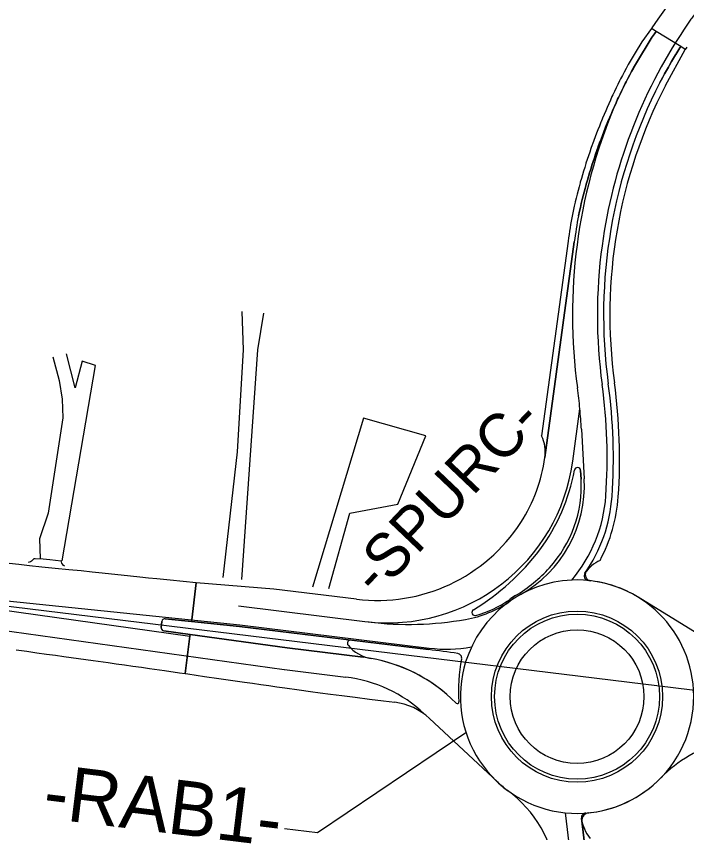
# Model space of a CAD drawing. Extents: x 1756435 to 1766932, y 416863 to 426859.
# Drawn here: x 1761886 to 1762317, y 423810 to 424335 of the extents above; entities that cross this region are included whole.
import ezdxf

# ---------------------------------------------------------------- set-up
doc = ezdxf.new("R2010")
doc.units = 0
for name, color, linetype in [('Exist Roads EOP', 7, 'Continuous'), ('Exist Roads EOP Other', 7, 'Continuous'), ('Exist Roads Soil', 7, 'Continuous'), ('Prop Horizontal Alignment', 7, 'Continuous'), ('Prop Horizontal Alignment Station Label', 7, 'Continuous'), ('Prop Lane Lines', 7, 'Continuous'), ('Prop Shade Light', 7, 'Continuous'), ('Prop Shade Medium', 7, 'Continuous'), ('Sheet Data Field CELL', 7, 'Continuous')]:
    doc.layers.add(name, color=color, linetype=linetype)

msp = doc.modelspace()

# ---------------------------------------------------------------- linework, layer by layer
at = {"layer": 'Exist Roads EOP'}
for points in [[(1762321.6, 424363.48), (1762316.63, 424357.5), (1762311.93, 424351.7), (1762307.26, 424345.52), (1762302.62, 424339), (1762298.3, 424332.9), (1762294.34, 424327.33), (1762294.14, 424327.04)], [(1762316.84, 424314.92), (1762315.88, 424313.48)], [(1762001.76, 423970.65), (1761993.3, 423971.54), (1761985.03, 423972.36), (1761976.32, 423973.22), (1761971.13, 423973.75), (1761965.4, 423974.36), (1761959.38, 423975), (1761953.37, 423975.64), (1761947.35, 423976.28), (1761941.34, 423976.92), (1761934.94, 423977.59), (1761927.78, 423978.33), (1761919.85, 423979.13), (1761911.15, 423979.99), (1761902.49, 423980.85), (1761894.67, 423981.65), (1761887.69, 423982.4), (1761881.56, 423983.08)], [(1761886.03, 423927.67), (1761892.76, 423926.72), (1761899.32, 423925.79), (1761905.56, 423924.9), (1761911.32, 423924.09), (1761916.59, 423923.35), (1761925.97, 423922.03), (1761935.4, 423920.72), (1761945.2, 423919.37), (1761950.33, 423918.66), (1761955.61, 423917.91), (1761961.05, 423917.14), (1761966.46, 423916.37), (1761971.64, 423915.63), (1761981.31, 423914.26), (1761991.01, 423912.87), (1761994.63, 423912.34)]]:
    msp.add_lwpolyline(points, dxfattribs=at)
at = {"layer": 'Exist Roads EOP Other'}
msp.add_lwpolyline([(1761917.32, 423981.35), (1761916.51, 423981.83), (1761915.9, 423982.5), (1761915.45, 423983.31), (1761915.18, 423984.26), (1761914.91, 423984.63), (1761911.31, 423985.07), (1761907.57, 423985.41), (1761903.26, 423985.8), (1761898.22, 423986.13), (1761897.38, 423986.01), (1761896.46, 423985.16), (1761895.79, 423984.67), (1761895.14, 423984.15), (1761893.73, 423983.83)], dxfattribs=at)
at = {"layer": 'Exist Roads Soil'}
for points in [[(1762031.09, 424145), (1762031.8, 424120.48), (1762027.9, 424054.77), (1762018.89, 423974.08)], [(1762031.04, 423972.72), (1762041.33, 424120.4), (1762045.19, 424143.92)], [(1761909.65, 424115.88), (1761913.69, 424100.69), (1761915.66, 424088.62), (1761915.96, 424076.72), (1761906.58, 424015.49), (1761900.99, 423998.89), (1761901.34, 423986.24)], [(1761915.53, 423984.75), (1761937.05, 424110.33), (1761928.51, 424113.21), (1761923.96, 424095.94), (1761918.37, 424117.88)], [(1762086.87, 423967.03), (1762100.49, 424015.55), (1762131.26, 424021.34), (1762149.29, 424065.09), (1762109.21, 424076.55), (1762076.39, 423967.96)]]:
    msp.add_lwpolyline(points, dxfattribs=at)
at = {"layer": 'Prop Horizontal Alignment'}
for p, q in [((1760837.84, 424083.41), (1762954.58, 423824.38)), ((1762243.6, 424048.79), (1762248.2, 424082.58)), ((1762238.73, 423822.92), (1762261.11, 423636.35))]:
    msp.add_line(p, q, dxfattribs=at)
for centre, radius, start, end in [((1762589.44, 424142.89), 330, 146.2017, 172.2542), ((1762589.44, 424142.89), 330, 172.2542, 187.7979), ((1761915.73, 424050.63), 350, 356.0542, 7.7979), ((1762124.7, 424064.96), 120, 263.0234, 352.2542), ((1762171.12, 424033.01), 94, 319.8828, 356.0542), ((1762246.4, 423897.52), 75, 92.5935, 162.7172), ((1762246.4, 423897.52), 75, 3.3296, 92.5935), ((1762246.4, 423897.52), 75, 162.7172, 264.1301), ((1762246.4, 423897.52), 75, 264.1301, 3.3296)]:
    msp.add_arc(centre, radius, start, end, dxfattribs=at)
msp.add_spline([(1762482.82, 424482.13), (1762480.32, 424480.29), (1762477.81, 424478.46), (1762475.3, 424476.62), (1762472.8, 424474.78), (1762470.29, 424472.94), (1762467.79, 424471.1), (1762465.29, 424469.25), (1762462.79, 424467.41), (1762460.29, 424465.56), (1762457.79, 424463.71), (1762455.3, 424461.85), (1762452.81, 424459.99), (1762450.32, 424458.13), (1762447.83, 424456.27), (1762445.35, 424454.4), (1762442.87, 424452.52), (1762440.4, 424450.64), (1762437.93, 424448.75), (1762435.46, 424446.86), (1762433, 424444.97), (1762430.54, 424443.06), (1762428.09, 424441.15), (1762425.64, 424439.24), (1762423.2, 424437.31), (1762420.77, 424435.38), (1762418.34, 424433.44), (1762415.92, 424431.49), (1762413.5, 424429.54), (1762411.09, 424427.57), (1762408.69, 424425.6), (1762406.3, 424423.62), (1762403.91, 424421.63), (1762401.54, 424419.62), (1762399.17, 424417.61), (1762396.81, 424415.59), (1762394.45, 424413.56), (1762392.11, 424411.52), (1762389.78, 424409.46), (1762387.46, 424407.4), (1762385.14, 424405.32), (1762382.84, 424403.23), (1762380.55, 424401.13), (1762378.27, 424399.02), (1762376, 424396.89), (1762373.75, 424394.76), (1762371.5, 424392.61), (1762369.27, 424390.44), (1762367.05, 424388.27), (1762364.85, 424386.08), (1762362.66, 424383.87), (1762360.48, 424381.65), (1762358.32, 424379.42), (1762356.17, 424377.17), (1762354.04, 424374.91), (1762351.92, 424372.64), (1762349.82, 424370.35), (1762347.74, 424368.04), (1762345.67, 424365.72), (1762343.62, 424363.39), (1762341.58, 424361.04), (1762339.57, 424358.67), (1762337.57, 424356.29), (1762335.59, 424353.89), (1762333.64, 424351.48), (1762331.7, 424349.05), (1762329.78, 424346.6), (1762327.88, 424344.14), (1762326, 424341.67), (1762324.15, 424339.17), (1762322.31, 424336.66), (1762320.5, 424334.14), (1762318.71, 424331.59), (1762316.95, 424329.04), (1762315.21, 424326.46)], degree=3, dxfattribs=at)
at = {"layer": 'Prop Horizontal Alignment Station Label'}
msp.add_lwpolyline([(1762058.43, 423812.73), (1762079.56, 423810.14), (1762175.03, 423874.46)], dxfattribs=at)
at = {"layer": 'Prop Lane Lines'}
for p, q in [((1762249.2, 424069.4), (1762250.99, 424037.51)), ((1761701.4, 423977.73), (1761997.58, 423936.5)), ((1761701.4, 423977.73), (1762029.68, 423943.61)), ((1761662.86, 423969.97), (1762058.2, 423914.93)), ((1762028.94, 423955.79), (1762110.12, 423945.85)), ((1762029.68, 423943.61), (1762151.32, 423928.72)), ((1762110.12, 423945.85), (1762112.82, 423945.52)), ((1762058.41, 423914.9), (1762097.76, 423910.09))]:
    msp.add_line(p, q, dxfattribs=at)
for centre, radius, start, end in [((1762589.44, 424142.89), 346, 157.2806, 187.7979), ((1761915.73, 424050.63), 334, 5.4882, 7.7979), ((1761915.73, 424050.63), 334, 3.2208, 5.4882), ((1762171.12, 424033.01), 80, 299.0561, 3.2208), ((1762162.25, 424018.05), 72, 279.9808, 304.9208), ((1762138.33, 424153.97), 210, 263.0234, 279.9808), ((1762162.25, 424018.05), 90, 263.0234, 280.4544), ((1762086.83, 423820.75), 90, 46.9754, 83.0234)]:
    msp.add_arc(centre, radius, start, end, dxfattribs=at)
at = {"layer": 'Prop Shade Light'}
for p, q in [((1762294.14, 424327.04), (1762288.05, 424318.39)), ((1762297.2, 424325.13), (1762294.14, 424327.04)), ((1762312.98, 424315.3), (1762297.2, 424325.13)), ((1762292.08, 424317.29), (1762293.41, 424319.4)), ((1762293.41, 424319.4), (1762292.08, 424317.29)), ((1762290.75, 424315.17), (1762292.08, 424317.29)), ((1762292.08, 424317.29), (1762290.75, 424315.17)), ((1762303.2, 424290.38), (1762315.88, 424313.48)), ((1762315.88, 424313.48), (1762312.98, 424315.3)), ((1762289.04, 424312.44), (1762287.77, 424310.29)), ((1762283.97, 424303.84), (1762282.71, 424301.68)), ((1762305.08, 424302.16), (1762305.86, 424303.49)), ((1762302.67, 424297.78), (1762301.46, 424295.59)), ((1762301.46, 424295.59), (1762302.67, 424297.78)), ((1762303.87, 424299.97), (1762302.67, 424297.78)), ((1762302.67, 424297.78), (1762303.87, 424299.97)), ((1762303.87, 424299.97), (1762305.08, 424302.16)), ((1762277.92, 424292.68), (1762277.3, 424291.51)), ((1762279.09, 424294.89), (1762277.92, 424292.68)), ((1762280.26, 424297.1), (1762279.09, 424294.89)), ((1762300.4, 424293.65), (1762299.64, 424292.21)), ((1762299.64, 424292.21), (1762300.4, 424293.65)), ((1762301.46, 424295.59), (1762300.4, 424293.65)), ((1762300.4, 424293.65), (1762301.46, 424295.59)), ((1762276.21, 424289.26), (1762275.13, 424287.02)), ((1762277.3, 424291.51), (1762276.21, 424289.26)), ((1762274.04, 424284.77), (1762275.13, 424287.02)), ((1762275.13, 424287.02), (1762274.04, 424284.77)), ((1762272.45, 424281.5), (1762271.45, 424279.21)), ((1762263.57, 424260.51), (1762264.46, 424262.84)), ((1762264.46, 424262.84), (1762263.57, 424260.51)), ((1762265.35, 424265.18), (1762264.46, 424262.84)), ((1762263.57, 424260.51), (1762262.69, 424258.18)), ((1762259.13, 424248.54), (1762259.93, 424250.91)), ((1762259.93, 424250.91), (1762260.03, 424251.17)), ((1762260.92, 424253.51), (1762260.03, 424251.17)), ((1762258.32, 424246.18), (1762257.52, 424243.81)), ((1762258.32, 424246.18), (1762259.13, 424248.54)), ((1762256.72, 424241.45), (1762255.92, 424239.08)), ((1762257.52, 424243.81), (1762256.72, 424241.45)), ((1762254.45, 424234.17), (1762255.16, 424236.57)), ((1762255.16, 424236.57), (1762254.45, 424234.17)), ((1762255.16, 424236.57), (1762255.88, 424238.96)), ((1762252.31, 424226.99), (1762253.02, 424229.39)), ((1762253.02, 424229.39), (1762252.31, 424226.99)), ((1762248.51, 424212), (1762249.05, 424214.44)), ((1762249.7, 424216.96), (1762249.08, 424214.54)), ((1762240.65, 424190.33), (1762223.63, 424065.2)), ((1762225.77, 424051.22), (1762244.61, 424189.8)), ((1762244.61, 424189.8), (1762225.77, 424051.22)), ((1762248.69, 424042.88), (1762249, 424037.4)), ((1762001.76, 423970.65), (1761998.84, 423946.81)), ((1761998.84, 423946.81), (1762001.76, 423970.65)), ((1762051.64, 423966.61), (1762001.76, 423970.65)), ((1762104.62, 423960.13), (1762051.64, 423966.61)), ((1762337.71, 423929.45), (1762285.66, 423961.43)), ((1761981.77, 423947.58), (1761998.72, 423945.82)), ((1761998.72, 423945.82), (1761981.77, 423947.58)), ((1761998.84, 423946.81), (1761998.72, 423945.82)), ((1761998.72, 423945.82), (1761998.84, 423946.81)), ((1761979.12, 423942.06), (1761979.58, 423945.83)), ((1761979.58, 423945.83), (1761979.12, 423942.06)), ((1761998.72, 423945.82), (1762029.58, 423942.61)), ((1762029.58, 423942.61), (1761998.72, 423945.82)), ((1762029.58, 423942.61), (1762150.96, 423927.76)), ((1762101.03, 423933.87), (1762029.58, 423942.61)), ((1761997.7, 423937.49), (1761980.83, 423939.84)), ((1761980.83, 423939.84), (1761997.7, 423937.49)), ((1761997.58, 423936.5), (1761994.63, 423912.34)), ((1761994.63, 423912.34), (1761997.58, 423936.5)), ((1761997.7, 423937.49), (1761997.58, 423936.5)), ((1761997.58, 423936.5), (1761997.7, 423937.49)), ((1762060.12, 423928.8), (1761997.7, 423937.49)), ((1761997.7, 423937.49), (1762060.12, 423928.8)), ((1762108.86, 423922.83), (1762060.12, 423928.8)), ((1762060.12, 423928.8), (1762108.86, 423922.83)), ((1762168.79, 423893.35), (1762165.51, 423896.42)), ((1762151.51, 423883.5), (1762195.23, 423842.69)), ((1762249.22, 423819.38), (1762271.04, 423637.54)), ((1762271.04, 423637.54), (1762249.22, 423819.38))]:
    msp.add_line(p, q, dxfattribs=at)
for points in [[(1762295.11, 424322.06), (1762296.51, 424324.13), (1762297.2, 424325.13)], [(1762297.2, 424325.13), (1762296.51, 424324.13), (1762295.11, 424322.06)], [(1762293.41, 424319.4), (1762294.74, 424321.52), (1762295.11, 424322.06)], [(1762295.11, 424322.06), (1762294.74, 424321.52), (1762293.41, 424319.4)], [(1762288.05, 424318.39), (1762287.36, 424317.3), (1762286.04, 424315.19), (1762285.62, 424314.52), (1762284.32, 424312.32), (1762283.06, 424310.17), (1762281.79, 424308.02), (1762280.53, 424305.86), (1762279.26, 424303.71), (1762279.11, 424303.46), (1762277.9, 424301.18), (1762276.73, 424298.97), (1762275.56, 424296.76), (1762274.39, 424294.56), (1762273.73, 424293.32), (1762272.61, 424291.01), (1762271.53, 424288.76), (1762270.44, 424286.51), (1762269.35, 424284.27), (1762268.82, 424283.17), (1762267.79, 424280.8), (1762266.79, 424278.51), (1762265.79, 424276.22), (1762264.8, 424273.93), (1762263.8, 424271.65), (1762262.8, 424269.36), (1762261.81, 424267.07), (1762261.64, 424266.69), (1762260.72, 424264.26), (1762259.84, 424261.93), (1762258.95, 424259.59), (1762258.06, 424257.26), (1762257.18, 424254.93), (1762256.29, 424252.59), (1762256.16, 424252.26), (1762255.34, 424249.83), (1762254.54, 424247.46), (1762253.73, 424245.1), (1762252.93, 424242.73), (1762252.13, 424240.37), (1762252.06, 424240.17), (1762251.33, 424237.71), (1762250.62, 424235.32), (1762249.9, 424232.92), (1762249.19, 424230.53), (1762248.48, 424228.14), (1762248.35, 424227.7), (1762247.7, 424225.21), (1762247.08, 424222.8), (1762246.45, 424220.38), (1762245.83, 424217.96), (1762245.2, 424215.54), (1762245.16, 424215.37), (1762244.61, 424212.86), (1762243.41, 424207.43)], [(1762283.97, 424303.84), (1762285.24, 424305.99), (1762286.51, 424308.14), (1762287.77, 424310.29), (1762289.04, 424312.44), (1762289.42, 424313.06), (1762290.75, 424315.17)], [(1762290.75, 424315.17), (1762289.42, 424313.06), (1762289.04, 424312.44)], [(1762312.98, 424315.3), (1762312.45, 424314.45), (1762311.13, 424312.33), (1762309.81, 424310.21)], [(1762309.81, 424310.21), (1762311.13, 424312.33), (1762312.45, 424314.45), (1762312.98, 424315.3)], [(1762287.77, 424310.29), (1762286.51, 424308.14), (1762285.24, 424305.99), (1762283.97, 424303.84)], [(1762309.81, 424310.21), (1762309.65, 424309.95), (1762308.38, 424307.8)], [(1762308.38, 424307.8), (1762309.65, 424309.95), (1762309.81, 424310.21)], [(1762280.26, 424297.1), (1762281.43, 424299.3), (1762282.6, 424301.51), (1762282.71, 424301.68), (1762283.97, 424303.84)], [(1762305.86, 424303.49), (1762305.08, 424302.16), (1762303.87, 424299.97)], [(1762308.38, 424307.8), (1762307.12, 424305.64), (1762305.86, 424303.49)], [(1762305.86, 424303.49), (1762307.12, 424305.64), (1762308.38, 424307.8)], [(1762282.71, 424301.68), (1762282.6, 424301.51), (1762281.43, 424299.3), (1762280.26, 424297.1)], [(1762275.13, 424287.02), (1762276.21, 424289.26), (1762277.3, 424291.51), (1762277.92, 424292.68)], [(1762277.92, 424292.68), (1762279.09, 424294.89), (1762280.26, 424297.1)], [(1762272.45, 424281.5), (1762272.95, 424282.52), (1762274.04, 424284.77)], [(1762274.04, 424284.77), (1762272.95, 424282.52), (1762272.45, 424281.5)], [(1762269.46, 424274.63), (1762270.46, 424276.92), (1762271.45, 424279.21), (1762272.45, 424281.5)], [(1762271.45, 424279.21), (1762270.46, 424276.92), (1762269.46, 424274.63)], [(1762269.46, 424274.63), (1762268.46, 424272.34), (1762267.47, 424270.05), (1762266.47, 424267.76), (1762265.47, 424265.47), (1762265.35, 424265.18)], [(1762267.47, 424270.05), (1762268.46, 424272.34), (1762269.46, 424274.63)], [(1762265.47, 424265.47), (1762266.47, 424267.76), (1762267.47, 424270.05)], [(1762264.46, 424262.84), (1762265.35, 424265.18), (1762265.47, 424265.47)], [(1762260.03, 424251.17), (1762260.92, 424253.51), (1762261.8, 424255.84), (1762262.69, 424258.18), (1762263.57, 424260.51)], [(1762262.69, 424258.18), (1762261.8, 424255.84), (1762260.92, 424253.51)], [(1762260.03, 424251.17), (1762259.93, 424250.91), (1762259.13, 424248.54), (1762258.32, 424246.18)], [(1762255.88, 424238.96), (1762255.92, 424239.08), (1762256.72, 424241.45), (1762257.52, 424243.81), (1762258.32, 424246.18)], [(1762255.92, 424239.08), (1762255.88, 424238.96), (1762255.16, 424236.57)], [(1762253.02, 424229.39), (1762253.74, 424231.78), (1762254.45, 424234.17)], [(1762254.45, 424234.17), (1762253.74, 424231.78), (1762253.02, 424229.39)], [(1762249.7, 424216.96), (1762250.33, 424219.38), (1762250.95, 424221.8), (1762251.58, 424224.21), (1762252.2, 424226.63), (1762252.31, 424226.99)], [(1762251.58, 424224.21), (1762250.95, 424221.8), (1762250.33, 424219.38), (1762249.7, 424216.96)], [(1762252.31, 424226.99), (1762252.2, 424226.63), (1762251.58, 424224.21)], [(1762249.08, 424214.54), (1762249.05, 424214.44), (1762248.51, 424212), (1762247.97, 424209.56), (1762247.33, 424206.64)], [(1762249.05, 424214.44), (1762249.08, 424214.54), (1762249.7, 424216.96)], [(1762247.33, 424206.64), (1762247.97, 424209.56), (1762248.51, 424212)], [(1762001.76, 423970.65), (1761993.3, 423971.54), (1761985.03, 423972.36), (1761976.32, 423973.22), (1761971.13, 423973.75), (1761965.4, 423974.36), (1761959.38, 423975), (1761953.37, 423975.64), (1761947.35, 423976.28), (1761941.34, 423976.92), (1761934.94, 423977.59), (1761927.78, 423978.33), (1761919.85, 423979.13), (1761911.15, 423979.99), (1761902.49, 423980.85), (1761894.67, 423981.65), (1761887.69, 423982.4), (1761881.56, 423983.08)], [(1761886.03, 423927.67), (1761892.76, 423926.72), (1761899.32, 423925.79), (1761905.56, 423924.9), (1761911.32, 423924.09), (1761916.59, 423923.35), (1761925.97, 423922.03), (1761935.4, 423920.72), (1761945.2, 423919.37), (1761950.33, 423918.66), (1761955.61, 423917.91), (1761961.05, 423917.14), (1761966.46, 423916.37), (1761971.64, 423915.63), (1761981.31, 423914.26), (1761991.01, 423912.87), (1761994.63, 423912.34)], [(1761994.63, 423912.34), (1761996.22, 423912.1), (1762001.67, 423911.29), (1762006.99, 423910.5), (1762016.15, 423909.18), (1762023.78, 423908.12), (1762032.69, 423906.88), (1762037.81, 423906.16), (1762043.11, 423905.41), (1762048.35, 423904.66), (1762053.54, 423903.93), (1762058.66, 423903.2), (1762067.86, 423901.9), (1762075.07, 423900.91), (1762081.42, 423900.07), (1762088.02, 423899.18), (1762095.36, 423898.22), (1762103.91, 423897.14), (1762113.01, 423896.01), (1762121.99, 423894.86), (1762129.26, 423893.93)]]:
    msp.add_lwpolyline(points, dxfattribs=at)
msp.add_circle((1762246.4, 423897.52), 55, dxfattribs=at)
for centre, radius, start, end in [((1762589.44, 424142.89), 326, 152.7405, 187.7979), ((1762589.44, 424142.89), 326, 152.7405, 187.7979), ((1762589.44, 424142.89), 322, 152.7405, 187.7979), ((1762589.44, 424142.89), 352, 169.4348, 172.2542), ((1762589.44, 424142.89), 348, 169.4456, 172.2542), ((1762589.44, 424142.89), 348, 169.4456, 172.2542), ((1761915.73, 424050.63), 354, 356.0542, 7.7979), ((1761915.73, 424050.63), 354, 356.0542, 7.7979), ((1761915.73, 424050.63), 358, 356.0542, 7.7979), ((1762200.99, 424054.59), 25, 352.2542, 25.1141), ((1762124.7, 424064.96), 102, 327.0789, 352.2542), ((1762124.7, 424064.96), 122, 323.2462, 349.6865), ((1762246.69, 424042.76), 2, 3.2208, 169.6865), ((1762171.12, 424033.01), 78, 317.5711, 3.2208), ((1762171.12, 424033.01), 98, 325.0529, 356.0542), ((1762171.12, 424033.01), 98, 325.0529, 356.0542), ((1762171.12, 424033.01), 102, 331.9959, 356.0542), ((1762117.98, 424069.31), 110, 263.0234, 327.0789), ((1762102.26, 424081.72), 150, 301.1308, 323.2462), ((1762271.94, 423962.56), 25, 115.5021, 145.0529), ((1762154.88, 424047.86), 100, 301.331, 317.5709), ((1762171.12, 424033.01), 78, 317.5708, 317.5711), ((1762271.94, 423962.56), 25, 142.4741, 145.0529), ((1762255.68, 423975.98), 4, 153.0822, 263.2523), ((1762253.91, 423975.16), 3, 145.0529, 264.4751), ((1762253.91, 423975.16), 3, 145.0529, 264.4751), ((1762246.4, 423897.52), 75, 58.4359, 84.4751), ((1762246.4, 423897.52), 75, 83.2523, 84.4751), ((1762246.4, 423897.52), 76, 121.331, 124.24), ((1762162.25, 424018.05), 71, 285.6344, 304.9208), ((1762246.4, 423897.52), 76, 124.24, 124.9208), ((1762180.85, 423951.61), 2, 121.1308, 285.6344), ((1761981.57, 423945.59), 2, 84.065, 173.0234), ((1761981.57, 423945.59), 2, 84.065, 173.0234), ((1761981.11, 423941.82), 2, 173.0234, 262.0738), ((1761981.11, 423941.82), 2, 173.0234, 262.0738), ((1762100.79, 423931.88), 2, 83.0234, 220.0522), ((1762118.39, 423946.68), 25, 220.0522, 260.0378), ((1762029.49, 422935.16), 1000, 81.93978, 83.0234), ((1762169.29, 423922.31), 3, 348.4278, 81.9398), ((1762096.59, 423822.58), 101, 46.9754, 83.0234), ((1762096.59, 423822.58), 101, 80.0383, 83.0234), ((1762270.19, 423901.65), 100, 168.4278, 184.2968), ((1762124.21, 423854.25), 40, 46.9754, 82.7488), ((1762169.48, 423894.08), 1, 226.9754, 4.2968), ((1762359.3, 423788.42), 82, 103.7157, 135.9791), ((1762246.4, 423897.52), 75, 226.9754, 233.4393), ((1762246.4, 423897.52), 75, 274.2674, 315.9791), ((1762154.07, 423773.02), 80, 6.8415, 53.4393), ((1762252.2, 423819.74), 3, 94.2674, 186.8416), ((1762252.2, 423819.74), 3, 94.2674, 186.8416), ((1762254.43, 423817.93), 5, 95.768, 179.5191), ((1762246.4, 423897.52), 75, 274.2674, 275.7648), ((1762274.05, 423822.36), 25, 186.8416, 219.7015), ((1762274.05, 423822.36), 25, 186.8416, 190.1146)]:
    msp.add_arc(centre, radius, start, end, dxfattribs=at)
at = {"layer": 'Prop Shade Medium'}
for p, q in [((1762249, 424037.4), (1762248.69, 424042.88)), ((1762150.96, 423927.76), (1762101.03, 423933.87)), ((1762165.51, 423896.42), (1762168.79, 423893.35))]:
    msp.add_line(p, q, dxfattribs=at)
msp.add_lwpolyline([(1762228.69, 423980.39), (1762228.69, 423980.39)], dxfattribs=at)
for radius in [53, 43]:
    msp.add_circle((1762246.4, 423897.52), radius, dxfattribs=at)
for centre, radius, start, end in [((1762124.7, 424064.96), 122, 323.2462, 349.6865), ((1762246.69, 424042.76), 2, 3.2208, 169.6865), ((1762171.12, 424033.01), 78, 317.5711, 3.2208), ((1762102.26, 424081.72), 150, 301.1308, 323.2462), ((1762154.88, 424047.86), 100, 301.331, 317.5709), ((1762246.4, 423897.52), 76, 121.331, 124.9208), ((1762162.25, 424018.05), 71, 285.6344, 304.9208), ((1762180.85, 423951.61), 2, 121.1308, 285.6344), ((1762100.79, 423931.88), 2, 83.0234, 220.0522), ((1762118.39, 423946.68), 25, 220.0522, 260.0382), ((1762029.49, 422935.16), 1000, 81.93978, 83.0234), ((1762169.29, 423922.31), 3, 348.4278, 81.9398), ((1762096.59, 423822.58), 101, 46.9754, 80.0382), ((1762270.19, 423901.65), 100, 168.4278, 184.2968), ((1762169.48, 423894.08), 1, 226.9754, 4.2968)]:
    msp.add_arc(centre, radius, start, end, dxfattribs=at)

# ---------------------------------------------------------------- texts
at = {"layer": 'Sheet Data Field CELL'}
for s, height, rotation, p in [('-SPURC-', 28, 46.4265, (1762117.7, 423961.21)), ('-RAB1-', 35, 353.0234, (1761902.3, 423819.69))]:
    msp.add_text(s, height=height, rotation=rotation, dxfattribs=at).set_placement(p)

doc.saveas('drawing.dxf')
